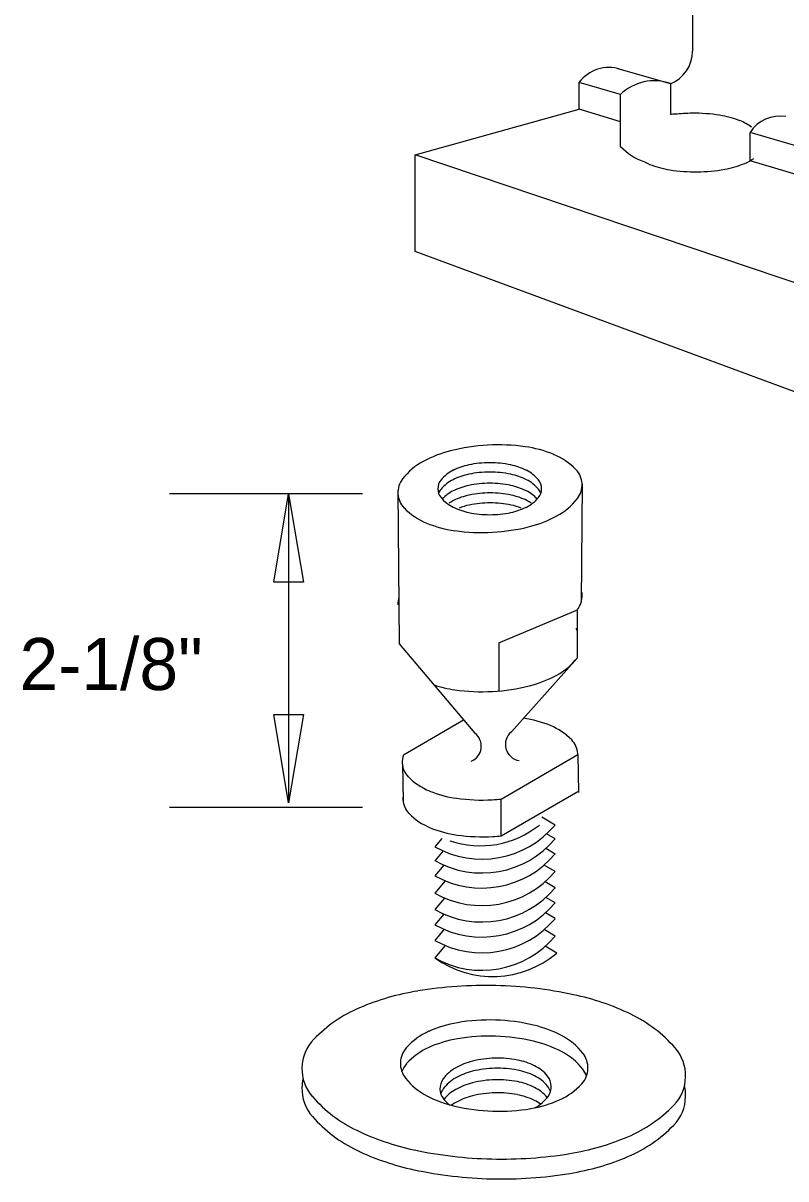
# Model space of a CAD drawing. Extents: x 12.3 to 19.6, y 5.9 to 16.2.
# Drawn here: x 15.732 to 16.612, y 8.371 to 9.704 of the extents above; entities that cross this region are included whole.
import ezdxf

# ---------------------------------------------------------------- set-up
doc = ezdxf.new("R2010")
doc.units = 0
for name, color, linetype in [('DETL-DIMS', 7, 'Continuous'), ('DETL-LINE', 7, 'Continuous'), ('DETL-NOTE', 7, 'Continuous')]:
    doc.layers.add(name, color=color, linetype=linetype)

msp = doc.modelspace()

# ---------------------------------------------------------------- linework, layer by layer
at = {"layer": 'DETL-DIMS'}
for p, q in [((16.1235, 9.161), (15.9009, 9.161)), ((16.0384, 9.161), (16.0384, 8.8045)), ((16.1235, 8.7992), (15.9009, 8.7992))]:
    msp.add_line(p, q, dxfattribs=at)
for points in [[(16.0555, 9.0589), (16.0214, 9.0589), (16.0384, 9.161)], [(16.0214, 8.9066), (16.0555, 8.9066), (16.0384, 8.8045)]]:
    msp.add_lwpolyline(points, close=True, dxfattribs=at)
at = {"layer": 'DETL-LINE'}
for p, q in [((16.5043, 10.0862), (16.5043, 9.6712)), ((16.479, 9.6339), (16.4185, 9.6512)), ((16.4213, 9.6213), (16.3735, 9.6353)), ((16.3735, 9.6044), (16.3735, 9.6353)), ((16.479, 9.6339), (16.479, 9.5984)), ((16.4213, 9.5616), (16.4213, 9.6213)), ((16.1845, 9.552), (16.3735, 9.6044)), ((16.4213, 9.59), (16.3735, 9.6044)), ((16.8756, 9.4888), (16.5709, 9.5777)), ((16.5709, 9.545), (16.5709, 9.5777)), ((16.9588, 9.291), (16.1845, 9.552)), ((16.1845, 9.4402), (16.1845, 9.552)), ((16.8892, 9.4491), (16.5709, 9.545)), ((16.9588, 9.154), (16.1845, 9.4402)), ((16.377, 9.1725), (16.3761, 9.036)), ((16.1646, 9.1646), (16.1661, 8.9879)), ((16.281, 8.989), (16.3716, 9.0273)), ((16.3717, 8.972), (16.3717, 9.0274)), ((16.1661, 8.9879), (16.2531, 8.8851)), ((16.281, 8.989), (16.281, 8.9336)), ((16.3716, 8.972), (16.2954, 8.8865)), ((16.1709, 8.8598), (16.2404, 8.9002)), ((16.249, 8.8526), (16.249, 8.8526)), ((16.2838, 8.809), (16.372, 8.8602)), ((16.372, 8.8602), (16.3728, 8.8165)), ((16.1697, 8.8492), (16.1705, 8.8068)), ((16.2838, 8.7665), (16.372, 8.8177)), ((16.2838, 8.7665), (16.2838, 8.809)), ((16.3459, 8.779), (16.3307, 8.7881)), ((16.2152, 8.7635), (16.2071, 8.754)), ((16.3459, 8.763), (16.3361, 8.7689)), ((16.2166, 8.7492), (16.2071, 8.7379)), ((16.3459, 8.7456), (16.3352, 8.752)), ((16.2175, 8.7328), (16.2071, 8.7205)), ((16.3459, 8.7254), (16.3333, 8.7329)), ((16.2192, 8.7147), (16.2071, 8.7003)), ((16.3459, 8.7066), (16.3343, 8.7136)), ((16.2184, 8.6948), (16.2071, 8.6815)), ((16.3459, 8.6892), (16.3352, 8.6956)), ((16.2175, 8.6764), (16.2071, 8.6641)), ((16.3459, 8.6711), (16.3347, 8.6777)), ((16.2179, 8.6588), (16.2071, 8.646)), ((16.3459, 8.6509), (16.3333, 8.6584)), ((16.2192, 8.6401), (16.2071, 8.6258)), ((16.348, 8.6314), (16.3346, 8.6393))]:
    msp.add_line(p, q, dxfattribs=at)
for centre, radius, start, end in [((16.4643, 9.6712), 0.0401, 291.5673, 0), ((16.408, 9.6092), 0.0433, 72.1536, 142.9577), ((16.4602, 9.5815), 0.0557, 70.2816, 134.3293), ((16.4836, 9.5294), 0.0692, 89.4943, 93.8399), ((16.506, 9.4084), 0.1914, 90.5832, 96.5224), ((16.506, 9.4084), 0.1914, 81.0685, 90.5832), ((16.5185, 9.488), 0.1108, 68.553, 81.0685), ((16.6052, 9.5558), 0.0407, 80.1406, 147.4655), ((16.5382, 9.5381), 0.0571, 53.014, 68.553), ((16.4724, 9.6103), 0.0706, 223.6212, 250.6253), ((16.4759, 9.594), 0.0571, 241.8396, 248.553), ((16.5428, 9.5947), 0.0571, 292.6134, 304.4253), ((16.4955, 9.644), 0.1108, 248.553, 261.0685), ((16.508, 9.7236), 0.1914, 261.0685, 270.5832), ((16.508, 9.7236), 0.1914, 270.5832, 280.098), ((16.5222, 9.6443), 0.1108, 280.098, 292.6134), ((16.2587, 9.0781), 0.1366, 104.1911, 118.4051), ((16.2803, 8.9927), 0.2247, 93.1202, 104.1911), ((16.2803, 8.9927), 0.2247, 82.0493, 93.1202), ((16.2924, 9.08), 0.1366, 67.8353, 82.0493), ((16.2301, 9.131), 0.0765, 118.4051, 141.8735), ((16.2705, 9.0774), 0.1194, 90, 101.7009), ((16.2705, 9.0774), 0.1194, 78.2991, 90), ((16.3151, 9.1356), 0.0765, 44.3669, 67.8353), ((16.2474, 9.1496), 0.043, 116.5651, 140.3607), ((16.2613, 9.1217), 0.0741, 101.7009, 116.5651), ((16.2613, 9.1109), 0.0741, 101.7009, 116.5651), ((16.2705, 9.0666), 0.1194, 90, 101.7009), ((16.2705, 9.0666), 0.1194, 78.2991, 90), ((16.2796, 9.1217), 0.0741, 63.4349, 78.2991), ((16.2796, 9.1109), 0.0741, 63.4349, 78.2991), ((16.2936, 9.1496), 0.043, 39.6393, 63.4349), ((16.3516, 9.1713), 0.0255, 3.1202, 44.3669), ((16.19, 9.1624), 0.0255, 141.8735, 183.1202), ((16.2265, 9.1668), 0.0159, 140.3607, 180), ((16.2474, 9.1388), 0.043, 116.5651, 140.3607), ((16.2613, 9.098), 0.0741, 101.7009, 116.5651), ((16.2705, 9.0537), 0.1194, 90, 101.7009), ((16.2705, 9.0537), 0.1194, 78.2991, 90), ((16.2796, 9.098), 0.0741, 63.4349, 78.2991), ((16.2936, 9.1388), 0.043, 39.6393, 63.4349), ((16.3144, 9.1668), 0.0159, 360, 39.6393), ((16.3516, 9.1713), 0.0255, 321.8735, 3.1202), ((16.19, 9.1624), 0.0255, 183.1202, 224.3669), ((16.2265, 9.1668), 0.0159, 180, 219.6393), ((16.2265, 9.1561), 0.0159, 140.3607, 160.1846), ((16.2474, 9.1841), 0.043, 219.6393, 243.4349), ((16.2474, 9.1259), 0.043, 116.5651, 137.3265), ((16.2618, 9.0869), 0.0741, 101.7009, 116.5651), ((16.271, 9.0426), 0.1194, 90, 101.7009), ((16.271, 9.0426), 0.1194, 78.2991, 90), ((16.2802, 9.0869), 0.0741, 63.4349, 78.2991), ((16.2936, 9.1259), 0.043, 42.6735, 63.4349), ((16.2936, 9.1841), 0.043, 296.5651, 320.3607), ((16.3144, 9.1668), 0.0159, 320.3607, 0), ((16.3144, 9.1561), 0.0159, 19.8154, 39.6393), ((16.2264, 9.1981), 0.0765, 224.3669, 247.8353), ((16.2479, 9.1147), 0.043, 116.5651, 124.0835), ((16.2613, 9.212), 0.0741, 243.4349, 258.2991), ((16.2618, 9.0754), 0.0741, 101.7009, 111.0033), ((16.271, 9.0311), 0.1194, 90, 101.7009), ((16.271, 9.0311), 0.1194, 78.2991, 90), ((16.2796, 9.212), 0.0741, 281.7009, 296.5651), ((16.2802, 9.0754), 0.0741, 68.9967, 78.2991), ((16.2941, 9.1147), 0.043, 55.9165, 63.4349), ((16.3115, 9.2027), 0.0765, 298.4051, 321.8735), ((16.2705, 9.2563), 0.1194, 258.2991, 270), ((16.2705, 9.2563), 0.1194, 270, 281.7009), ((16.2829, 9.2556), 0.1366, 284.1911, 298.4051), ((16.2491, 9.2537), 0.1366, 247.8353, 262.0493), ((16.2613, 9.341), 0.2247, 262.0493, 273.1202), ((16.2613, 9.341), 0.2247, 273.1202, 284.1911), ((16.3516, 9.0431), 0.0255, 3.1202, 15.3169), ((16.19, 9.0343), 0.0255, 162.6405, 183.1202), ((16.3516, 9.0431), 0.0255, 321.8735, 3.1202), ((16.3516, 8.9877), 0.0255, 38.0014, 44.3669), ((16.3115, 9.0192), 0.0765, 298.4051, 321.8735), ((16.3516, 8.9877), 0.0255, 321.8735, 321.9986), ((16.2829, 9.072), 0.1366, 284.1911, 298.4051), ((16.2491, 9.0702), 0.1366, 251.6999, 262.0493), ((16.2613, 9.1574), 0.2247, 262.0493, 273.1202), ((16.2613, 9.1574), 0.2247, 273.1202, 284.1911), ((16.2798, 8.6901), 0.214, 82.0493, 82.0908), ((16.2914, 8.7732), 0.1301, 67.8353, 82.0493), ((16.313, 8.8262), 0.0728, 44.3669, 67.8353), ((16.2418, 8.87), 0.0189, 292.4347, 53.0065), ((16.3073, 8.8719), 0.0188, 129.1655, 261.1608), ((16.3477, 8.8601), 0.0243, 3.1202, 44.3669), ((16.1938, 8.8517), 0.0243, 160.5994, 183.1202), ((16.1938, 8.8517), 0.0243, 183.1202, 224.3669), ((16.3477, 8.8601), 0.0243, 0.1573, 3.1202), ((16.2285, 8.8857), 0.0728, 224.3669, 247.8353), ((16.1946, 8.8094), 0.0243, 176.2002, 183.1202), ((16.2501, 8.9387), 0.1301, 247.8353, 262.0493), ((16.2617, 9.0218), 0.214, 262.0493, 273.1202), ((16.1946, 8.8094), 0.0243, 183.1202, 224.3669), ((16.2617, 9.0218), 0.214, 273.1202, 275.9189), ((16.2294, 8.8433), 0.0728, 224.3669, 247.8353), ((16.2509, 8.8963), 0.1301, 247.8353, 262.0493), ((16.2614, 8.8502), 0.1105, 240.5948, 319.9009), ((16.2597, 8.8638), 0.1087, 251.153, 308.7624), ((16.2614, 8.8342), 0.1105, 240.5948, 319.9009), ((16.2625, 8.9794), 0.214, 262.0493, 273.1202), ((16.2625, 8.9794), 0.214, 273.1202, 275.6963), ((16.2614, 8.8168), 0.1105, 240.5948, 319.9009), ((16.2614, 8.7966), 0.1105, 240.5948, 319.9009), ((16.2614, 8.7777), 0.1105, 240.5948, 319.9009), ((16.2614, 8.7603), 0.1105, 240.5948, 319.9009), ((16.2614, 8.7422), 0.1105, 240.5948, 319.9009), ((16.2614, 8.722), 0.1105, 240.5948, 319.9009), ((16.274, 8.7194), 0.115, 234.4998, 310.0333), ((16.2344, 8.2988), 0.2926, 99.2321, 112.9408), ((16.2659, 8.1051), 0.4889, 88.6369, 99.2321), ((16.2659, 8.1051), 0.4889, 78.0417, 88.6369), ((16.3066, 8.2971), 0.2926, 64.3331, 78.0417), ((16.1826, 8.4212), 0.1597, 112.9408, 136.1093), ((16.3641, 8.4169), 0.1597, 41.1645, 64.3331), ((16.256, 8.4164), 0.1366, 99.5736, 114.0913), ((16.2703, 8.3316), 0.2226, 88.2112, 99.5736), ((16.2703, 8.3316), 0.2226, 76.8488, 88.2112), ((16.2898, 8.4153), 0.1366, 62.3311, 76.8488), ((16.1028, 8.498), 0.049, 136.1093, 178.6369), ((16.232, 8.4701), 0.0778, 114.0913, 137.7207), ((16.256, 8.3978), 0.1366, 99.5736, 114.0913), ((16.2703, 8.313), 0.2226, 88.2112, 99.5736), ((16.2703, 8.313), 0.2226, 76.8488, 88.2112), ((16.3172, 8.4674), 0.0778, 38.7017, 62.3311), ((16.1946, 8.5041), 0.0272, 137.7207, 178.2112), ((16.232, 8.4515), 0.0778, 114.0913, 137.7207), ((16.2898, 8.3967), 0.1366, 62.3311, 76.8488), ((16.3172, 8.4488), 0.0778, 38.7017, 62.3311), ((16.4475, 8.4898), 0.049, 358.6369, 41.1645), ((16.1946, 8.5041), 0.0272, 178.2112, 218.7017), ((16.1946, 8.4855), 0.0272, 137.7207, 160.0349), ((16.269, 8.4319), 0.077, 103.8602, 119.3743), ((16.2796, 8.389), 0.1212, 91.5065, 103.8602), ((16.2796, 8.389), 0.1212, 79.1528, 91.5065), ((16.2879, 8.4324), 0.077, 63.6387, 79.1528), ((16.3566, 8.499), 0.0272, 358.2112, 38.7017), ((16.1028, 8.498), 0.049, 178.6369, 221.1645), ((16.2539, 8.4587), 0.0463, 119.3743, 143.4322), ((16.269, 8.4203), 0.077, 103.8602, 119.3743), ((16.2796, 8.3774), 0.1212, 91.5065, 103.8602), ((16.2796, 8.3774), 0.1212, 79.1528, 91.5065), ((16.2879, 8.4208), 0.077, 63.6387, 79.1528), ((16.3015, 8.46), 0.0463, 39.5808, 63.6387), ((16.3015, 8.4484), 0.0463, 39.5808, 63.6387), ((16.3566, 8.499), 0.0272, 317.7207, 358.2112), ((16.3566, 8.4804), 0.0272, 19.9651, 38.7017), ((16.1028, 8.4751), 0.049, 166.4892, 178.6369), ((16.234, 8.5357), 0.0778, 218.7017, 242.3311), ((16.2319, 8.475), 0.0189, 143.4322, 181.5065), ((16.2539, 8.4471), 0.0463, 119.3743, 143.4322), ((16.269, 8.407), 0.077, 103.8602, 119.3743), ((16.2796, 8.3641), 0.1212, 91.5065, 103.8602), ((16.2796, 8.3641), 0.1212, 79.1528, 91.5065), ((16.2879, 8.4075), 0.077, 63.6387, 79.1528), ((16.3015, 8.435), 0.0463, 40.205, 63.6387), ((16.3226, 8.4774), 0.0189, 1.5065, 39.5808), ((16.3226, 8.4658), 0.0189, 17.8482, 39.5808), ((16.3226, 8.4774), 0.0189, 323.4322, 1.5065), ((16.3192, 8.533), 0.0778, 294.0913, 317.7207), ((16.4475, 8.4898), 0.049, 316.1093, 358.6369), ((16.4475, 8.4669), 0.049, 358.6369, 13.5108), ((16.1028, 8.4751), 0.049, 178.6369, 221.1645), ((16.1862, 8.5709), 0.1597, 221.1645, 244.3331), ((16.2613, 8.5878), 0.1366, 242.3311, 256.8488), ((16.2319, 8.475), 0.0189, 181.5065, 219.5808), ((16.2319, 8.4634), 0.0189, 143.4322, 162.1518), ((16.2539, 8.4338), 0.0463, 119.3743, 141.5294), ((16.269, 8.3919), 0.077, 103.8602, 119.3743), ((16.2796, 8.3491), 0.1212, 91.5065, 103.8602), ((16.2796, 8.3491), 0.1212, 79.1528, 91.5065), ((16.2879, 8.3924), 0.077, 63.6387, 79.1528), ((16.3006, 8.4937), 0.0463, 299.3743, 323.4322), ((16.4475, 8.4669), 0.049, 316.1093, 358.6369), ((16.253, 8.4925), 0.0463, 219.5808, 231.184), ((16.2539, 8.4187), 0.0463, 119.3743, 126.7911), ((16.2809, 8.6715), 0.2226, 256.8488, 268.2112), ((16.2809, 8.6715), 0.2226, 268.2112, 279.5736), ((16.2952, 8.5868), 0.1366, 279.5736, 294.0913), ((16.3015, 8.42), 0.0463, 53.4904, 63.6387), ((16.2856, 8.5205), 0.077, 298.6321, 299.3743), ((16.3677, 8.5666), 0.1597, 292.9408, 316.1093), ((16.1862, 8.548), 0.1597, 221.1645, 244.3331), ((16.2437, 8.6907), 0.2926, 244.3331, 258.0417), ((16.3677, 8.5437), 0.1597, 292.9408, 316.1093), ((16.3159, 8.689), 0.2926, 279.2321, 292.9408), ((16.2437, 8.6678), 0.2926, 244.3331, 258.0417), ((16.2844, 8.8827), 0.4889, 258.0417, 268.6369), ((16.2844, 8.8827), 0.4889, 268.6369, 279.2321), ((16.3159, 8.6661), 0.2926, 279.2321, 292.9408), ((16.2844, 8.8598), 0.4889, 258.0417, 268.6369), ((16.2844, 8.8598), 0.4889, 268.6369, 279.2321)]:
    msp.add_arc(centre, radius, start, end, dxfattribs=at)

# ---------------------------------------------------------------- texts
at = {"layer": 'DETL-NOTE'}
msp.add_text('2-1/8"', height=0.06, dxfattribs=at).set_placement((15.728, 8.9347))

doc.saveas('drawing.dxf')
